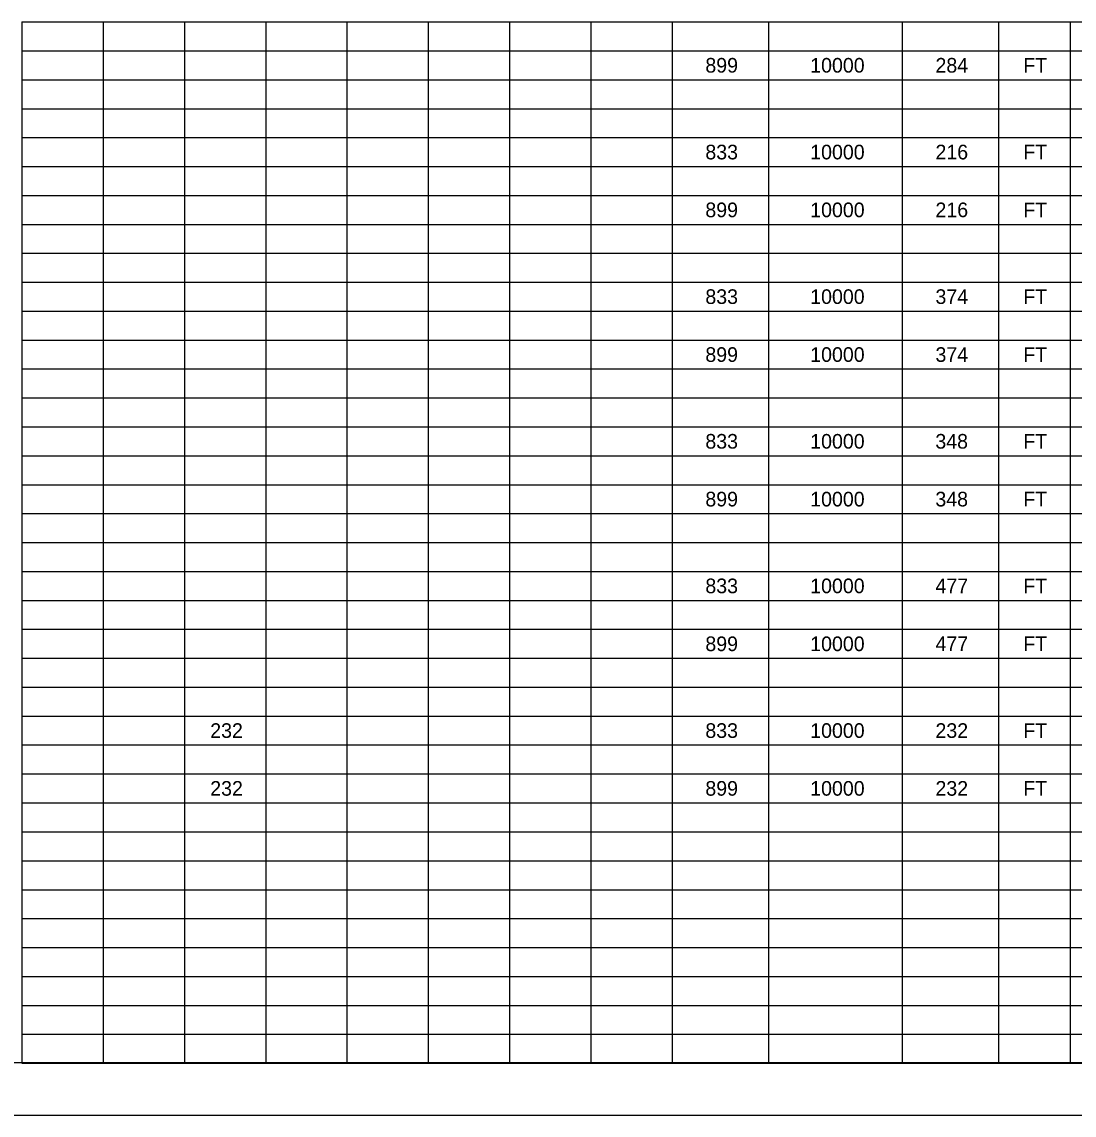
# Model space of a CAD drawing. Extents: x 0.2 to 34.2, y 0 to 22.
# Drawn here: x 13.45 to 23.51, y 0.03 to 10.48 of the extents above; entities that cross this region are included whole.
import ezdxf

# ---------------------------------------------------------------- set-up
doc = ezdxf.new("R2010")
doc.units = 0
for name, color, linetype in [('Default', 7, 'Continuous'), ('SH_Border', 7, 'Continuous'), ('SH_Cut_Line', 7, 'Continuous')]:
    doc.layers.add(name, color=color, linetype=linetype)

msp = doc.modelspace()

# ---------------------------------------------------------------- linework, layer by layer
at = {"layer": 'Default'}
for p, q in [((13.445, 10.483), (14.223, 10.483)), ((13.445, 10.483), (13.445, 10.207)), ((14.223, 10.483), (16.555, 10.483)), ((14.223, 10.483), (14.223, 10.207)), ((15, 10.483), (15, 10.207)), ((15.778, 10.483), (15.778, 10.207)), ((16.555, 10.483), (32.196, 10.483)), ((16.555, 10.483), (16.555, 10.207)), ((17.332, 10.483), (17.332, 10.207)), ((18.11, 10.483), (18.11, 10.207)), ((18.887, 10.483), (18.887, 10.207)), ((19.665, 10.483), (19.665, 10.207)), ((20.587, 10.483), (20.587, 10.207)), ((21.865, 10.483), (21.865, 10.207)), ((22.788, 10.483), (22.788, 10.207)), ((23.473, 10.483), (23.473, 10.207)), ((13.445, 10.207), (14.223, 10.207)), ((13.445, 10.207), (13.445, 9.93)), ((14.223, 10.207), (16.555, 10.207)), ((14.223, 10.207), (14.223, 9.93)), ((15, 10.207), (15, 9.93)), ((15.778, 10.207), (15.778, 9.93)), ((16.555, 10.207), (32.196, 10.207)), ((16.555, 10.207), (16.555, 9.93)), ((17.332, 10.207), (17.332, 9.93)), ((18.11, 10.207), (18.11, 9.93)), ((18.887, 10.207), (18.887, 9.93)), ((19.665, 10.207), (19.665, 9.93)), ((20.587, 10.207), (20.587, 9.93)), ((21.865, 10.207), (21.865, 9.93)), ((22.788, 10.207), (22.788, 9.93)), ((23.473, 10.207), (23.473, 9.93)), ((13.445, 9.93), (14.223, 9.93)), ((13.445, 9.93), (13.445, 9.653)), ((14.223, 9.93), (16.555, 9.93)), ((14.223, 9.93), (14.223, 9.653)), ((15, 9.93), (15, 9.653)), ((15.778, 9.93), (15.778, 9.653)), ((16.555, 9.93), (32.196, 9.93)), ((16.555, 9.93), (16.555, 9.653)), ((17.332, 9.93), (17.332, 9.653)), ((18.11, 9.93), (18.11, 9.653)), ((18.887, 9.93), (18.887, 9.653)), ((19.665, 9.93), (19.665, 9.653)), ((20.587, 9.93), (20.587, 9.653)), ((21.865, 9.93), (21.865, 9.653)), ((22.788, 9.93), (22.788, 9.653)), ((23.473, 9.93), (23.473, 9.653)), ((13.445, 9.653), (14.223, 9.653)), ((13.445, 9.653), (13.445, 9.377)), ((14.223, 9.653), (16.555, 9.653)), ((14.223, 9.653), (14.223, 9.377)), ((15, 9.653), (15, 9.377)), ((15.778, 9.653), (15.778, 9.377)), ((16.555, 9.653), (32.196, 9.653)), ((16.555, 9.653), (16.555, 9.377)), ((17.332, 9.653), (17.332, 9.377)), ((18.11, 9.653), (18.11, 9.377)), ((18.887, 9.653), (18.887, 9.377)), ((19.665, 9.653), (19.665, 9.377)), ((20.587, 9.653), (20.587, 9.377)), ((21.865, 9.653), (21.865, 9.377)), ((22.788, 9.653), (22.788, 9.377)), ((23.473, 9.653), (23.473, 9.377)), ((13.445, 9.377), (14.223, 9.377)), ((13.445, 9.377), (13.445, 9.1)), ((14.223, 9.377), (16.555, 9.377)), ((14.223, 9.377), (14.223, 9.1)), ((15, 9.377), (15, 9.1)), ((15.778, 9.377), (15.778, 9.1)), ((16.555, 9.377), (32.196, 9.377)), ((16.555, 9.377), (16.555, 9.1)), ((17.332, 9.377), (17.332, 9.1)), ((18.11, 9.377), (18.11, 9.1)), ((18.887, 9.377), (18.887, 9.1)), ((19.665, 9.377), (19.665, 9.1)), ((20.587, 9.377), (20.587, 9.1)), ((21.865, 9.377), (21.865, 9.1)), ((22.788, 9.377), (22.788, 9.1)), ((23.473, 9.377), (23.473, 9.1)), ((13.445, 9.1), (14.223, 9.1)), ((13.445, 9.1), (13.445, 8.823)), ((14.223, 9.1), (16.555, 9.1)), ((14.223, 9.1), (14.223, 8.823)), ((15, 9.1), (15, 8.823)), ((15.778, 9.1), (15.778, 8.823)), ((16.555, 9.1), (32.196, 9.1)), ((16.555, 9.1), (16.555, 8.823)), ((17.332, 9.1), (17.332, 8.823)), ((18.11, 9.1), (18.11, 8.823)), ((18.887, 9.1), (18.887, 8.823)), ((19.665, 9.1), (19.665, 8.823)), ((20.587, 9.1), (20.587, 8.823)), ((21.865, 9.1), (21.865, 8.823)), ((22.788, 9.1), (22.788, 8.823)), ((23.473, 9.1), (23.473, 8.823)), ((13.445, 8.823), (14.223, 8.823)), ((13.445, 8.823), (13.445, 8.546)), ((14.223, 8.823), (16.555, 8.823)), ((14.223, 8.823), (14.223, 8.546)), ((15, 8.823), (15, 8.546)), ((15.778, 8.823), (15.778, 8.546)), ((16.555, 8.823), (32.196, 8.823)), ((16.555, 8.823), (16.555, 8.546)), ((17.332, 8.823), (17.332, 8.546)), ((18.11, 8.823), (18.11, 8.546)), ((18.887, 8.823), (18.887, 8.546)), ((19.665, 8.823), (19.665, 8.546)), ((20.587, 8.823), (20.587, 8.546)), ((21.865, 8.823), (21.865, 8.546)), ((22.788, 8.823), (22.788, 8.546)), ((23.473, 8.823), (23.473, 8.546)), ((13.445, 8.546), (14.223, 8.546)), ((13.445, 8.546), (13.445, 8.27)), ((14.223, 8.546), (16.555, 8.546)), ((14.223, 8.546), (14.223, 8.27)), ((15, 8.546), (15, 8.27)), ((15.778, 8.546), (15.778, 8.27)), ((16.555, 8.546), (32.196, 8.546)), ((16.555, 8.546), (16.555, 8.27)), ((17.332, 8.546), (17.332, 8.27)), ((18.11, 8.546), (18.11, 8.27)), ((18.887, 8.546), (18.887, 8.27)), ((19.665, 8.546), (19.665, 8.27)), ((20.587, 8.546), (20.587, 8.27)), ((21.865, 8.546), (21.865, 8.27)), ((22.788, 8.546), (22.788, 8.27)), ((23.473, 8.546), (23.473, 8.27)), ((13.445, 8.27), (14.223, 8.27)), ((13.445, 8.27), (13.445, 7.993)), ((14.223, 8.27), (16.555, 8.27)), ((14.223, 8.27), (14.223, 7.993)), ((15, 8.27), (15, 7.993)), ((15.778, 8.27), (15.778, 7.993)), ((16.555, 8.27), (32.196, 8.27)), ((16.555, 8.27), (16.555, 7.993)), ((17.332, 8.27), (17.332, 7.993)), ((18.11, 8.27), (18.11, 7.993)), ((18.887, 8.27), (18.887, 7.993)), ((19.665, 8.27), (19.665, 7.993)), ((20.587, 8.27), (20.587, 7.993)), ((21.865, 8.27), (21.865, 7.993)), ((22.788, 8.27), (22.788, 7.993)), ((23.473, 8.27), (23.473, 7.993)), ((13.445, 7.993), (14.223, 7.993)), ((13.445, 7.993), (13.445, 7.716)), ((14.223, 7.993), (16.555, 7.993)), ((14.223, 7.993), (14.223, 7.716)), ((15, 7.993), (15, 7.716)), ((15.778, 7.993), (15.778, 7.716)), ((16.555, 7.993), (32.196, 7.993)), ((16.555, 7.993), (16.555, 7.716)), ((17.332, 7.993), (17.332, 7.716)), ((18.11, 7.993), (18.11, 7.716)), ((18.887, 7.993), (18.887, 7.716)), ((19.665, 7.993), (19.665, 7.716)), ((20.587, 7.993), (20.587, 7.716)), ((21.865, 7.993), (21.865, 7.716)), ((22.788, 7.993), (22.788, 7.716)), ((23.473, 7.993), (23.473, 7.716)), ((13.445, 7.716), (14.223, 7.716)), ((13.445, 7.716), (13.445, 7.44)), ((14.223, 7.716), (16.555, 7.716)), ((14.223, 7.716), (14.223, 7.44)), ((15, 7.716), (15, 7.44)), ((15.778, 7.716), (15.778, 7.44)), ((16.555, 7.716), (32.196, 7.716)), ((16.555, 7.716), (16.555, 7.44)), ((17.332, 7.716), (17.332, 7.44)), ((18.11, 7.716), (18.11, 7.44)), ((18.887, 7.716), (18.887, 7.44)), ((19.665, 7.716), (19.665, 7.44)), ((20.587, 7.716), (20.587, 7.44)), ((21.865, 7.716), (21.865, 7.44)), ((22.788, 7.716), (22.788, 7.44)), ((23.473, 7.716), (23.473, 7.44)), ((13.445, 7.44), (14.223, 7.44)), ((13.445, 7.44), (13.445, 7.163)), ((14.223, 7.44), (16.555, 7.44)), ((14.223, 7.44), (14.223, 7.163)), ((15, 7.44), (15, 7.163)), ((15.778, 7.44), (15.778, 7.163)), ((16.555, 7.44), (32.196, 7.44)), ((16.555, 7.44), (16.555, 7.163)), ((17.332, 7.44), (17.332, 7.163)), ((18.11, 7.44), (18.11, 7.163)), ((18.887, 7.44), (18.887, 7.163)), ((19.665, 7.44), (19.665, 7.163)), ((20.587, 7.44), (20.587, 7.163)), ((21.865, 7.44), (21.865, 7.163)), ((22.788, 7.44), (22.788, 7.163)), ((23.473, 7.44), (23.473, 7.163)), ((13.445, 7.163), (14.223, 7.163)), ((13.445, 7.163), (13.445, 6.886)), ((14.223, 7.163), (16.555, 7.163)), ((14.223, 7.163), (14.223, 6.886)), ((15, 7.163), (15, 6.886)), ((15.778, 7.163), (15.778, 6.886)), ((16.555, 7.163), (32.196, 7.163)), ((16.555, 7.163), (16.555, 6.886)), ((17.332, 7.163), (17.332, 6.886)), ((18.11, 7.163), (18.11, 6.886)), ((18.887, 7.163), (18.887, 6.886)), ((19.665, 7.163), (19.665, 6.886)), ((20.587, 7.163), (20.587, 6.886)), ((21.865, 7.163), (21.865, 6.886)), ((22.788, 7.163), (22.788, 6.886)), ((23.473, 7.163), (23.473, 6.886)), ((13.445, 6.886), (14.223, 6.886)), ((13.445, 6.886), (13.445, 6.609)), ((14.223, 6.886), (16.555, 6.886)), ((14.223, 6.886), (14.223, 6.609)), ((15, 6.886), (15, 6.609)), ((15.778, 6.886), (15.778, 6.609)), ((16.555, 6.886), (32.196, 6.886)), ((16.555, 6.886), (16.555, 6.609)), ((17.332, 6.886), (17.332, 6.609)), ((18.11, 6.886), (18.11, 6.609)), ((18.887, 6.886), (18.887, 6.609)), ((19.665, 6.886), (19.665, 6.609)), ((20.587, 6.886), (20.587, 6.609)), ((21.865, 6.886), (21.865, 6.609)), ((22.788, 6.886), (22.788, 6.609)), ((23.473, 6.886), (23.473, 6.609)), ((13.445, 6.609), (14.223, 6.609)), ((13.445, 6.609), (13.445, 6.333)), ((14.223, 6.609), (16.555, 6.609)), ((14.223, 6.609), (14.223, 6.333)), ((15, 6.609), (15, 6.333)), ((15.778, 6.609), (15.778, 6.333)), ((16.555, 6.609), (32.196, 6.609)), ((16.555, 6.609), (16.555, 6.333)), ((17.332, 6.609), (17.332, 6.333)), ((18.11, 6.609), (18.11, 6.333)), ((18.887, 6.609), (18.887, 6.333)), ((19.665, 6.609), (19.665, 6.333)), ((20.587, 6.609), (20.587, 6.333)), ((21.865, 6.609), (21.865, 6.333)), ((22.788, 6.609), (22.788, 6.333)), ((23.473, 6.609), (23.473, 6.333)), ((13.445, 6.333), (14.223, 6.333)), ((13.445, 6.333), (13.445, 5.779)), ((14.223, 6.333), (16.555, 6.333)), ((14.223, 6.333), (14.223, 5.779)), ((15, 6.333), (15, 5.779)), ((15.778, 6.333), (15.778, 5.779)), ((16.555, 6.333), (32.196, 6.333)), ((16.555, 6.333), (16.555, 5.779)), ((17.332, 6.333), (17.332, 5.779)), ((18.11, 6.333), (18.11, 5.779)), ((18.887, 6.333), (18.887, 5.779)), ((19.665, 6.333), (19.665, 5.779)), ((20.587, 6.333), (20.587, 5.779)), ((21.865, 6.333), (21.865, 5.779)), ((22.788, 6.333), (22.788, 5.779)), ((23.473, 6.333), (23.473, 5.779)), ((13.445, 6.056), (14.223, 6.056)), ((14.223, 6.056), (16.555, 6.056)), ((16.555, 6.056), (32.196, 6.056)), ((13.445, 5.779), (14.223, 5.779)), ((13.445, 5.779), (13.445, 5.503)), ((14.223, 5.779), (16.555, 5.779)), ((14.223, 5.779), (14.223, 5.503)), ((15, 5.779), (15, 5.503)), ((15.778, 5.779), (15.778, 5.503)), ((16.555, 5.779), (32.196, 5.779)), ((16.555, 5.779), (16.555, 5.503)), ((17.332, 5.779), (17.332, 5.503)), ((18.11, 5.779), (18.11, 5.503)), ((18.887, 5.779), (18.887, 5.503)), ((19.665, 5.779), (19.665, 5.503)), ((20.587, 5.779), (20.587, 5.503)), ((21.865, 5.779), (21.865, 5.503)), ((22.788, 5.779), (22.788, 5.503)), ((23.473, 5.779), (23.473, 5.503)), ((13.445, 5.503), (14.223, 5.503)), ((13.445, 5.503), (13.445, 4.396)), ((14.223, 5.503), (16.555, 5.503)), ((14.223, 5.503), (14.223, 4.396)), ((15, 5.503), (15, 4.396)), ((15.778, 5.503), (15.778, 4.396)), ((16.555, 5.503), (32.196, 5.503)), ((16.555, 5.503), (16.555, 4.396)), ((17.332, 5.503), (17.332, 4.396)), ((18.11, 5.503), (18.11, 4.396)), ((18.887, 5.503), (18.887, 4.396)), ((19.665, 5.503), (19.665, 4.396)), ((20.587, 5.503), (20.587, 4.396)), ((21.865, 5.503), (21.865, 4.396)), ((22.788, 5.503), (22.788, 4.396)), ((23.473, 5.503), (23.473, 4.396)), ((13.445, 5.226), (14.223, 5.226)), ((14.223, 5.226), (16.555, 5.226)), ((16.555, 5.226), (32.196, 5.226)), ((13.445, 4.949), (14.223, 4.949)), ((14.223, 4.949), (16.555, 4.949)), ((16.555, 4.949), (32.196, 4.949)), ((13.445, 4.673), (14.223, 4.673)), ((14.223, 4.673), (16.555, 4.673)), ((16.555, 4.673), (32.196, 4.673)), ((13.445, 4.396), (14.223, 4.396)), ((13.445, 4.396), (13.445, 4.119)), ((14.223, 4.396), (16.555, 4.396)), ((14.223, 4.396), (14.223, 4.119)), ((15, 4.396), (15, 4.119)), ((15.778, 4.396), (15.778, 4.119)), ((16.555, 4.396), (32.196, 4.396)), ((16.555, 4.396), (16.555, 4.119)), ((17.332, 4.396), (17.332, 4.119)), ((18.11, 4.396), (18.11, 4.119)), ((18.887, 4.396), (18.887, 4.119)), ((19.665, 4.396), (19.665, 4.119)), ((20.587, 4.396), (20.587, 4.119)), ((21.865, 4.396), (21.865, 4.119)), ((22.788, 4.396), (22.788, 4.119)), ((23.473, 4.396), (23.473, 4.119)), ((13.445, 4.119), (14.223, 4.119)), ((13.445, 4.119), (13.445, 3.012)), ((14.223, 4.119), (16.555, 4.119)), ((14.223, 4.119), (14.223, 3.012)), ((15, 4.119), (15, 3.012)), ((15.778, 4.119), (15.778, 3.012)), ((16.555, 4.119), (32.196, 4.119)), ((16.555, 4.119), (16.555, 3.012)), ((17.332, 4.119), (17.332, 3.012)), ((18.11, 4.119), (18.11, 3.012)), ((18.887, 4.119), (18.887, 3.012)), ((19.665, 4.119), (19.665, 3.012)), ((20.587, 4.119), (20.587, 3.012)), ((21.865, 4.119), (21.865, 3.012)), ((22.788, 4.119), (22.788, 3.012)), ((23.473, 4.119), (23.473, 3.012)), ((13.445, 3.842), (14.223, 3.842)), ((14.223, 3.842), (16.555, 3.842)), ((16.555, 3.842), (32.196, 3.842)), ((13.445, 3.566), (14.223, 3.566)), ((14.223, 3.566), (16.555, 3.566)), ((16.555, 3.566), (32.196, 3.566)), ((13.445, 3.289), (14.223, 3.289)), ((14.223, 3.289), (16.555, 3.289)), ((16.555, 3.289), (32.196, 3.289)), ((13.445, 3.012), (14.223, 3.012)), ((13.445, 3.012), (13.445, 2.736)), ((14.223, 3.012), (16.555, 3.012)), ((14.223, 3.012), (14.223, 2.736)), ((15, 3.012), (15, 2.736)), ((15.778, 3.012), (15.778, 2.736)), ((16.555, 3.012), (32.196, 3.012)), ((16.555, 3.012), (16.555, 2.736)), ((17.332, 3.012), (17.332, 2.736)), ((18.11, 3.012), (18.11, 2.736)), ((18.887, 3.012), (18.887, 2.736)), ((19.665, 3.012), (19.665, 2.736)), ((20.587, 3.012), (20.587, 2.736)), ((21.865, 3.012), (21.865, 2.736)), ((22.788, 3.012), (22.788, 2.736)), ((23.473, 3.012), (23.473, 2.736)), ((13.445, 2.736), (14.223, 2.736)), ((13.445, 2.736), (13.445, 1.629)), ((14.223, 2.736), (16.555, 2.736)), ((14.223, 2.736), (14.223, 1.629)), ((15, 2.736), (15, 1.629)), ((15.778, 2.736), (15.778, 1.629)), ((16.555, 2.736), (32.196, 2.736)), ((16.555, 2.736), (16.555, 1.629)), ((17.332, 2.736), (17.332, 1.629)), ((18.11, 2.736), (18.11, 1.629)), ((18.887, 2.736), (18.887, 1.629)), ((19.665, 2.736), (19.665, 1.629)), ((20.587, 2.736), (20.587, 1.629)), ((21.865, 2.736), (21.865, 1.629)), ((22.788, 2.736), (22.788, 1.629)), ((23.473, 2.736), (23.473, 1.629)), ((13.445, 2.459), (14.223, 2.459)), ((14.223, 2.459), (16.555, 2.459)), ((16.555, 2.459), (32.196, 2.459)), ((13.445, 2.182), (14.223, 2.182)), ((14.223, 2.182), (16.555, 2.182)), ((16.555, 2.182), (32.196, 2.182)), ((13.445, 1.905), (14.223, 1.905)), ((14.223, 1.905), (16.555, 1.905)), ((16.555, 1.905), (32.196, 1.905)), ((13.445, 1.629), (14.223, 1.629)), ((13.445, 1.629), (13.445, 1.352)), ((14.223, 1.629), (16.555, 1.629)), ((14.223, 1.629), (14.223, 1.352)), ((15, 1.629), (15, 1.352)), ((15.778, 1.629), (15.778, 1.352)), ((16.555, 1.629), (32.196, 1.629)), ((16.555, 1.629), (16.555, 1.352)), ((17.332, 1.629), (17.332, 1.352)), ((18.11, 1.629), (18.11, 1.352)), ((18.887, 1.629), (18.887, 1.352)), ((19.665, 1.629), (19.665, 1.352)), ((20.587, 1.629), (20.587, 1.352)), ((21.865, 1.629), (21.865, 1.352)), ((22.788, 1.629), (22.788, 1.352)), ((23.473, 1.629), (23.473, 1.352)), ((13.445, 1.352), (14.223, 1.352)), ((13.445, 1.352), (13.445, 0.522)), ((14.223, 1.352), (16.555, 1.352)), ((14.223, 1.352), (14.223, 0.522)), ((15, 1.352), (15, 0.522)), ((15.778, 1.352), (15.778, 0.522)), ((16.555, 1.352), (32.196, 1.352)), ((16.555, 1.352), (16.555, 0.522)), ((17.332, 1.352), (17.332, 0.522)), ((18.11, 1.352), (18.11, 0.522)), ((18.887, 1.352), (18.887, 0.522)), ((19.665, 1.352), (19.665, 0.522)), ((20.587, 1.352), (20.587, 0.522)), ((21.865, 1.352), (21.865, 0.522)), ((22.788, 1.352), (22.788, 0.522)), ((23.473, 1.352), (23.473, 0.522)), ((13.445, 1.075), (14.223, 1.075)), ((14.223, 1.075), (16.555, 1.075)), ((16.555, 1.075), (32.196, 1.075)), ((13.445, 0.799), (14.223, 0.799)), ((14.223, 0.799), (16.555, 0.799)), ((16.555, 0.799), (32.196, 0.799)), ((13.445, 0.522), (14.223, 0.522)), ((14.223, 0.522), (16.555, 0.522)), ((16.555, 0.522), (32.196, 0.522))]:
    msp.add_line(p, q, dxfattribs=at)
at = {"layer": 'SH_Border'}
msp.add_lwpolyline([(1.692, 21.525), (33.692, 21.525), (33.692, 0.525), (1.692, 0.525)], close=True, dxfattribs=at)
at = {"layer": 'SH_Cut_Line'}
msp.add_lwpolyline([(0.192, 0.025), (34.192, 0.025), (34.192, 22.025), (0.192, 22.025)], close=True, dxfattribs=at)

# ---------------------------------------------------------------- texts
at = {"layer": 'Default'}
for s, p in [('899', (19.983, 9.998)), ('10000', (20.986, 9.998)), ('284', (22.184, 9.998)), ('FT', (23.024, 9.998)), ('833', (19.983, 9.168)), ('10000', (20.986, 9.168)), ('216', (22.184, 9.168)), ('FT', (23.024, 9.168)), ('899', (19.983, 8.615)), ('10000', (20.986, 8.615)), ('216', (22.184, 8.615)), ('FT', (23.024, 8.615)), ('833', (19.983, 7.785)), ('10000', (20.986, 7.785)), ('374', (22.184, 7.785)), ('FT', (23.024, 7.785)), ('899', (19.983, 7.231)), ('10000', (20.986, 7.231)), ('374', (22.184, 7.231)), ('FT', (23.024, 7.231)), ('833', (19.983, 6.401)), ('10000', (20.986, 6.401)), ('348', (22.183, 6.401)), ('FT', (23.024, 6.401)), ('899', (19.983, 5.848)), ('10000', (20.986, 5.848)), ('348', (22.183, 5.848)), ('FT', (23.024, 5.848)), ('833', (19.983, 5.018)), ('10000', (20.986, 5.018)), ('477', (22.184, 5.018)), ('FT', (23.024, 5.018)), ('899', (19.983, 4.464)), ('10000', (20.986, 4.464)), ('477', (22.184, 4.464)), ('FT', (23.024, 4.464)), ('232', (15.247, 3.634)), ('833', (19.983, 3.634)), ('10000', (20.986, 3.634)), ('232', (22.184, 3.634)), ('FT', (23.024, 3.634)), ('232', (15.247, 3.081)), ('899', (19.983, 3.081)), ('10000', (20.986, 3.081)), ('232', (22.184, 3.081)), ('FT', (23.024, 3.081))]:
    msp.add_text(s, height=0.14, dxfattribs=at).set_placement(p)

doc.saveas('drawing.dxf')
